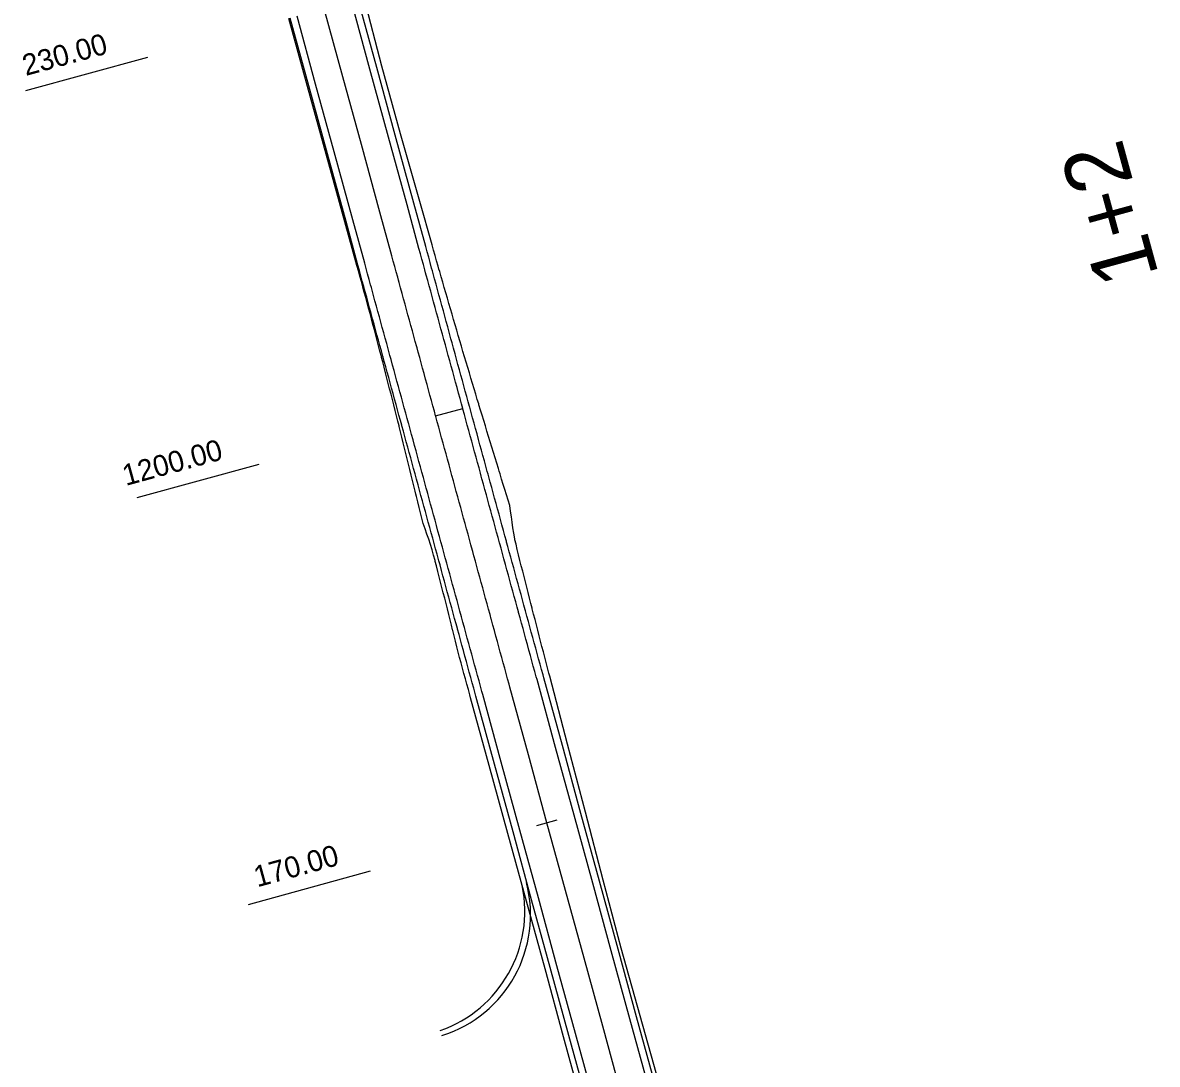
# Model space of a CAD drawing. Extents: x -550605 to -538780, y -1102367 to -1093705.
# Drawn here: x -547384 to -547303.3, y -1101097.8 to -1101023.7 of the extents above; entities that cross this region are included whole.
import ezdxf

# ---------------------------------------------------------------- set-up
doc = ezdxf.new("R2010")
doc.units = 0
for name, color, linetype in [('SIT - hrany vozovky', 7, 'Continuous'), ('SIT - oblouky - hrany', 7, 'Continuous'), ('SIT - oblouky - koruna', 7, 'Continuous'), ('SIT - osa cesty', 7, 'Continuous'), ('SIT - paty násypů', 7, 'Continuous'), ('SIT - staničení po 100m', 7, 'Continuous'), ('SIT - staničení po 30m', 7, 'Continuous')]:
    doc.layers.add(name, color=color, linetype=linetype)

msp = doc.modelspace()

# ---------------------------------------------------------------- linework, layer by layer
at = {"layer": 'SIT - hrany vozovky'}
for points in [[(-547339.531, -1101099.38), (-547340.851, -1101094.558), (-547342.171, -1101089.735), (-547343.491, -1101084.913), (-547344.81, -1101080.09), (-547346.13, -1101075.267), (-547347.45, -1101070.445), (-547347.506, -1101070.243), (-547347.61, -1101069.862), (-547347.714, -1101069.481), (-547347.818, -1101069.1), (-547347.923, -1101068.72), (-547348.027, -1101068.339), (-547348.131, -1101067.958), (-547348.235, -1101067.577), (-547348.339, -1101067.197), (-547348.444, -1101066.816), (-547348.548, -1101066.435), (-547348.652, -1101066.054), (-547348.756, -1101065.674), (-547348.77, -1101065.622), (-547348.86, -1101065.293), (-547348.965, -1101064.912), (-547349.069, -1101064.531), (-547349.173, -1101064.151), (-547349.277, -1101063.77), (-547349.382, -1101063.389), (-547349.486, -1101063.008), (-547349.59, -1101062.627), (-547349.694, -1101062.247), (-547349.798, -1101061.866), (-547349.903, -1101061.485), (-547350.007, -1101061.104), (-547350.09, -1101060.799), (-547350.111, -1101060.724), (-547350.215, -1101060.343), (-547350.319, -1101059.962), (-547350.424, -1101059.581), (-547350.528, -1101059.201), (-547350.632, -1101058.82), (-547350.736, -1101058.439), (-547350.841, -1101058.058), (-547350.945, -1101057.678), (-547351.049, -1101057.297), (-547351.153, -1101056.916), (-547351.257, -1101056.535), (-547351.362, -1101056.155), (-547351.41, -1101055.977), (-547351.466, -1101055.774), (-547351.57, -1101055.393), (-547351.674, -1101055.012), (-547351.778, -1101054.631), (-547351.883, -1101054.251), (-547351.987, -1101053.87), (-547352.091, -1101053.489), (-547352.195, -1101053.108), (-547352.3, -1101052.728), (-547352.404, -1101052.347), (-547352.508, -1101051.966), (-547352.612, -1101051.585), (-547352.716, -1101051.205), (-547352.73, -1101051.154), (-547352.821, -1101050.824), (-547352.925, -1101050.443), (-547353.029, -1101050.062), (-547353.133, -1101049.682), (-547353.237, -1101049.301), (-547353.342, -1101048.92), (-547353.446, -1101048.539), (-547353.55, -1101048.159), (-547353.654, -1101047.778), (-547353.759, -1101047.397), (-547353.863, -1101047.016), (-547353.967, -1101046.635), (-547354.05, -1101046.332), (-547354.071, -1101046.255), (-547354.175, -1101045.874), (-547354.28, -1101045.493), (-547354.384, -1101045.112), (-547354.488, -1101044.732), (-547354.592, -1101044.351), (-547354.696, -1101043.97), (-547354.801, -1101043.589), (-547354.905, -1101043.209), (-547355.009, -1101042.828), (-547355.113, -1101042.447), (-547355.218, -1101042.066), (-547355.322, -1101041.686), (-547355.37, -1101041.509), (-547355.426, -1101041.305), (-547355.53, -1101040.924), (-547355.634, -1101040.543), (-547355.739, -1101040.163), (-547355.843, -1101039.782), (-547356.69, -1101036.686), (-547358.01, -1101031.864), (-547359.33, -1101027.041), (-547360.65, -1101022.218)], [(-547339.048, -1101099.248), (-547340.368, -1101094.426), (-547341.688, -1101089.603), (-547343.008, -1101084.781), (-547344.328, -1101079.958), (-547345.648, -1101075.135), (-547346.968, -1101070.313), (-547347.023, -1101070.111), (-547347.128, -1101069.73), (-547347.232, -1101069.349), (-547347.336, -1101068.968), (-547347.44, -1101068.588), (-547347.544, -1101068.207), (-547347.649, -1101067.826), (-547347.753, -1101067.445), (-547347.857, -1101067.065), (-547347.961, -1101066.684), (-547348.066, -1101066.303), (-547348.17, -1101065.922), (-547348.274, -1101065.542), (-547348.288, -1101065.49), (-547348.378, -1101065.161), (-547348.482, -1101064.78), (-547348.587, -1101064.399), (-547348.691, -1101064.019), (-547348.795, -1101063.638), (-547348.899, -1101063.257), (-547349.003, -1101062.876), (-547349.108, -1101062.495), (-547349.212, -1101062.115), (-547349.316, -1101061.734), (-547349.42, -1101061.353), (-547349.525, -1101060.972), (-547349.608, -1101060.667), (-547349.629, -1101060.592), (-547349.733, -1101060.211), (-547349.837, -1101059.83), (-547349.941, -1101059.449), (-547350.046, -1101059.069), (-547350.15, -1101058.688), (-547350.254, -1101058.307), (-547350.358, -1101057.926), (-547350.462, -1101057.546), (-547350.567, -1101057.165), (-547350.671, -1101056.784), (-547350.775, -1101056.403), (-547350.879, -1101056.023), (-547350.928, -1101055.845), (-547350.984, -1101055.642), (-547351.088, -1101055.261), (-547351.192, -1101054.88), (-547351.296, -1101054.499), (-547351.4, -1101054.119), (-547351.505, -1101053.738), (-547351.609, -1101053.357), (-547351.713, -1101052.976), (-547351.817, -1101052.596), (-547351.921, -1101052.215), (-547352.026, -1101051.834), (-547352.13, -1101051.453), (-547352.234, -1101051.073), (-547352.248, -1101051.022), (-547352.338, -1101050.692), (-547352.443, -1101050.311), (-547352.547, -1101049.93), (-547352.651, -1101049.55), (-547352.755, -1101049.169), (-547352.859, -1101048.788), (-547352.964, -1101048.407), (-547353.068, -1101048.027), (-547353.172, -1101047.646), (-547353.276, -1101047.265), (-547353.38, -1101046.884), (-547353.485, -1101046.503), (-547353.568, -1101046.2), (-547353.589, -1101046.123), (-547353.693, -1101045.742), (-547353.797, -1101045.361), (-547353.902, -1101044.98), (-547354.006, -1101044.6), (-547354.11, -1101044.219), (-547354.214, -1101043.838), (-547354.318, -1101043.457), (-547354.423, -1101043.077), (-547354.527, -1101042.696), (-547354.631, -1101042.315), (-547354.735, -1101041.934), (-547354.839, -1101041.554), (-547354.888, -1101041.377), (-547354.944, -1101041.173), (-547355.048, -1101040.792), (-547355.152, -1101040.411), (-547355.256, -1101040.031), (-547355.361, -1101039.65), (-547356.208, -1101036.554), (-547357.528, -1101031.732), (-547358.848, -1101026.909), (-547360.168, -1101022.086)], [(-547343.389, -1101100.436), (-547344.709, -1101095.614), (-547346.029, -1101090.791), (-547347.349, -1101085.968), (-547348.669, -1101081.146), (-547349.989, -1101076.323), (-547351.308, -1101071.501), (-547351.364, -1101071.299), (-547351.468, -1101070.918), (-547351.572, -1101070.537), (-547351.676, -1101070.156), (-547351.781, -1101069.776), (-547351.885, -1101069.395), (-547351.989, -1101069.014), (-547352.093, -1101068.633), (-547352.197, -1101068.253), (-547352.302, -1101067.872), (-547352.406, -1101067.491), (-547352.51, -1101067.11), (-547352.614, -1101066.73), (-547352.628, -1101066.678), (-547352.719, -1101066.349), (-547352.823, -1101065.968), (-547352.927, -1101065.587), (-547353.031, -1101065.207), (-547353.135, -1101064.826), (-547353.24, -1101064.445), (-547353.344, -1101064.064), (-547353.448, -1101063.683), (-547353.552, -1101063.303), (-547353.656, -1101062.922), (-547353.761, -1101062.541), (-547353.865, -1101062.16), (-547353.948, -1101061.855), (-547353.969, -1101061.78), (-547354.073, -1101061.399), (-547354.178, -1101061.018), (-547354.282, -1101060.637), (-547354.386, -1101060.257), (-547354.49, -1101059.876), (-547354.594, -1101059.495), (-547354.699, -1101059.114), (-547354.803, -1101058.734), (-547354.907, -1101058.353), (-547355.011, -1101057.972), (-547355.115, -1101057.591), (-547355.22, -1101057.21), (-547355.268, -1101057.033), (-547355.324, -1101056.83), (-547355.428, -1101056.449), (-547355.532, -1101056.068), (-547355.637, -1101055.687), (-547355.741, -1101055.307), (-547355.845, -1101054.926), (-547355.949, -1101054.545), (-547356.053, -1101054.164), (-547356.158, -1101053.784), (-547356.262, -1101053.403), (-547356.366, -1101053.022), (-547356.47, -1101052.641), (-547356.574, -1101052.261), (-547356.588, -1101052.21), (-547356.679, -1101051.88), (-547356.783, -1101051.499), (-547356.887, -1101051.118), (-547356.991, -1101050.738), (-547357.096, -1101050.357), (-547357.2, -1101049.976), (-547357.304, -1101049.595), (-547357.408, -1101049.214), (-547357.512, -1101048.834), (-547357.617, -1101048.453), (-547357.721, -1101048.072), (-547357.825, -1101047.691), (-547357.908, -1101047.387), (-547357.929, -1101047.311), (-547358.033, -1101046.93), (-547358.138, -1101046.549), (-547358.242, -1101046.168), (-547358.346, -1101045.788), (-547358.45, -1101045.407), (-547358.555, -1101045.026), (-547358.659, -1101044.645), (-547358.763, -1101044.265), (-547358.867, -1101043.884), (-547358.971, -1101043.503), (-547359.076, -1101043.122), (-547359.18, -1101042.742), (-547359.228, -1101042.565), (-547359.284, -1101042.361), (-547359.388, -1101041.98), (-547359.492, -1101041.599), (-547359.597, -1101041.218), (-547359.701, -1101040.838), (-547360.548, -1101037.742), (-547361.868, -1101032.92), (-547363.188, -1101028.097), (-547364.508, -1101023.274)], [(-547343.871, -1101100.568), (-547345.191, -1101095.746), (-547346.511, -1101090.923), (-547347.831, -1101086.1), (-547349.151, -1101081.278), (-547350.471, -1101076.455), (-547351.791, -1101071.633), (-547351.846, -1101071.431), (-547351.95, -1101071.05), (-547352.054, -1101070.669), (-547352.159, -1101070.288), (-547352.263, -1101069.908), (-547352.367, -1101069.527), (-547352.471, -1101069.146), (-547352.576, -1101068.765), (-547352.68, -1101068.385), (-547352.784, -1101068.004), (-547352.888, -1101067.623), (-547352.992, -1101067.242), (-547353.097, -1101066.862), (-547353.111, -1101066.81), (-547353.201, -1101066.481), (-547353.305, -1101066.1), (-547353.409, -1101065.719), (-547353.513, -1101065.338), (-547353.618, -1101064.958), (-547353.722, -1101064.577), (-547353.826, -1101064.196), (-547353.93, -1101063.815), (-547354.035, -1101063.435), (-547354.139, -1101063.054), (-547354.243, -1101062.673), (-547354.347, -1101062.292), (-547354.431, -1101061.987), (-547354.451, -1101061.912), (-547354.556, -1101061.531), (-547354.66, -1101061.15), (-547354.764, -1101060.769), (-547354.868, -1101060.389), (-547354.972, -1101060.008), (-547355.077, -1101059.627), (-547355.181, -1101059.246), (-547355.285, -1101058.866), (-547355.389, -1101058.485), (-547355.494, -1101058.104), (-547355.598, -1101057.723), (-547355.702, -1101057.342), (-547355.751, -1101057.165), (-547355.806, -1101056.962), (-547355.91, -1101056.581), (-547356.015, -1101056.2), (-547356.119, -1101055.819), (-547356.223, -1101055.439), (-547356.327, -1101055.058), (-547356.431, -1101054.677), (-547356.536, -1101054.296), (-547356.64, -1101053.916), (-547356.744, -1101053.535), (-547356.848, -1101053.154), (-547356.953, -1101052.773), (-547357.057, -1101052.393), (-547357.071, -1101052.342), (-547357.161, -1101052.012), (-547357.265, -1101051.631), (-547357.369, -1101051.25), (-547357.474, -1101050.87), (-547357.578, -1101050.489), (-547357.682, -1101050.108), (-547357.786, -1101049.727), (-547357.89, -1101049.346), (-547357.995, -1101048.966), (-547358.099, -1101048.585), (-547358.203, -1101048.204), (-547358.307, -1101047.823), (-547358.391, -1101047.519), (-547358.412, -1101047.443), (-547358.516, -1101047.062), (-547358.62, -1101046.681), (-547358.724, -1101046.3), (-547358.828, -1101045.92), (-547358.933, -1101045.539), (-547359.037, -1101045.158), (-547359.141, -1101044.777), (-547359.245, -1101044.397), (-547359.349, -1101044.016), (-547359.454, -1101043.635), (-547359.558, -1101043.254), (-547359.662, -1101042.874), (-547359.71, -1101042.697), (-547359.766, -1101042.493), (-547359.871, -1101042.112), (-547359.975, -1101041.731), (-547360.079, -1101041.35), (-547360.183, -1101040.97), (-547361.03, -1101037.874), (-547362.35, -1101033.052), (-547363.67, -1101028.229), (-547364.99, -1101023.406)]]:
    msp.add_lwpolyline(points, dxfattribs=at)
at = {"layer": 'SIT - oblouky - hrany'}
msp.add_arc((-547357.314, -1101086.912), 9, 289.38382, 11.65556, dxfattribs=at)
at = {"layer": 'SIT - oblouky - koruna'}
msp.add_arc((-547356.908, -1101087.171), 9, 287.46315, 14.77752, dxfattribs=at)
at = {"layer": 'SIT - osa cesty'}
msp.add_lwpolyline([(-547341.46, -1101099.908), (-547342.78, -1101095.086), (-547344.1, -1101090.263), (-547345.42, -1101085.441), (-547346.74, -1101080.618), (-547348.059, -1101075.795), (-547349.379, -1101070.973), (-547349.435, -1101070.771), (-547349.539, -1101070.39), (-547349.643, -1101070.009), (-547349.747, -1101069.628), (-547349.852, -1101069.248), (-547349.956, -1101068.867), (-547350.06, -1101068.486), (-547350.164, -1101068.105), (-547350.268, -1101067.725), (-547350.373, -1101067.344), (-547350.477, -1101066.963), (-547350.581, -1101066.582), (-547350.685, -1101066.202), (-547350.699, -1101066.15), (-547350.789, -1101065.821), (-547350.894, -1101065.44), (-547350.998, -1101065.059), (-547351.102, -1101064.679), (-547351.206, -1101064.298), (-547351.311, -1101063.917), (-547351.415, -1101063.536), (-547351.519, -1101063.155), (-547351.623, -1101062.775), (-547351.727, -1101062.394), (-547351.832, -1101062.013), (-547351.936, -1101061.632), (-547352.019, -1101061.327), (-547352.04, -1101061.252), (-547352.144, -1101060.871), (-547352.248, -1101060.49), (-547352.353, -1101060.109), (-547352.457, -1101059.729), (-547352.561, -1101059.348), (-547352.665, -1101058.967), (-547352.77, -1101058.586), (-547352.874, -1101058.206), (-547352.978, -1101057.825), (-547353.082, -1101057.444), (-547353.186, -1101057.063), (-547353.291, -1101056.683), (-547353.339, -1101056.505), (-547353.395, -1101056.302), (-547353.499, -1101055.921), (-547353.603, -1101055.54), (-547353.707, -1101055.159), (-547353.812, -1101054.779), (-547353.916, -1101054.398), (-547354.02, -1101054.017), (-547354.124, -1101053.636), (-547354.229, -1101053.256), (-547354.333, -1101052.875), (-547354.437, -1101052.494), (-547354.541, -1101052.113), (-547354.645, -1101051.733), (-547354.659, -1101051.682), (-547354.75, -1101051.352), (-547354.854, -1101050.971), (-547354.958, -1101050.59), (-547355.062, -1101050.21), (-547355.167, -1101049.829), (-547355.271, -1101049.448), (-547355.375, -1101049.067), (-547355.479, -1101048.687), (-547355.583, -1101048.306), (-547355.688, -1101047.925), (-547355.792, -1101047.544), (-547355.896, -1101047.163), (-547355.979, -1101046.86), (-547356, -1101046.783), (-547356.104, -1101046.402), (-547356.209, -1101046.021), (-547356.313, -1101045.64), (-547356.417, -1101045.26), (-547356.521, -1101044.879), (-547356.626, -1101044.498), (-547356.73, -1101044.117), (-547356.834, -1101043.737), (-547356.938, -1101043.356), (-547357.042, -1101042.975), (-547357.147, -1101042.594), (-547357.251, -1101042.214), (-547357.299, -1101042.037), (-547357.355, -1101041.833), (-547357.459, -1101041.452), (-547357.563, -1101041.071), (-547357.668, -1101040.691), (-547357.772, -1101040.31), (-547358.619, -1101037.214), (-547359.939, -1101032.392), (-547361.259, -1101027.569), (-547362.579, -1101022.746)], dxfattribs=at)
at = {"layer": 'SIT - paty násypů'}
for points in [[(-547338.755, -1101099.168), (-547340.125, -1101094.359), (-547341.465, -1101089.542), (-547342.735, -1101084.706), (-547344.005, -1101079.869), (-547345.275, -1101075.033), (-547346.545, -1101070.197), (-547346.599, -1101069.994), (-547346.699, -1101069.613), (-547346.799, -1101069.231), (-547346.898, -1101068.849), (-547346.998, -1101068.467), (-547347.097, -1101068.085), (-547347.197, -1101067.702), (-547347.296, -1101067.32), (-547347.394, -1101066.938), (-547347.493, -1101066.556), (-547347.592, -1101066.173), (-547347.69, -1101065.791), (-547347.788, -1101065.409), (-547347.801, -1101065.357), (-547347.886, -1101065.026), (-547347.984, -1101064.644), (-547348.081, -1101064.261), (-547348.178, -1101063.878), (-547348.275, -1101063.496), (-547348.372, -1101063.113), (-547348.469, -1101062.73), (-547348.566, -1101062.347), (-547348.66, -1101061.964), (-547348.755, -1101061.58), (-547348.849, -1101061.197), (-547348.943, -1101060.813), (-547349.018, -1101060.506), (-547349.036, -1101060.43), (-547349.1, -1101060.038), (-547349.157, -1101059.644), (-547349.215, -1101059.251), (-547349.272, -1101058.857), (-547349.329, -1101058.463), (-547349.389, -1101058.07), (-547349.501, -1101057.692), (-547349.615, -1101057.314), (-547349.732, -1101056.936), (-547349.848, -1101056.559), (-547349.965, -1101056.181), (-547350.081, -1101055.804), (-547350.135, -1101055.628), (-547350.197, -1101055.426), (-547350.313, -1101055.049), (-547350.428, -1101054.671), (-547350.544, -1101054.294), (-547350.659, -1101053.916), (-547350.775, -1101053.538), (-547350.89, -1101053.161), (-547351.006, -1101052.783), (-547351.121, -1101052.405), (-547351.236, -1101052.027), (-547351.351, -1101051.649), (-547351.465, -1101051.271), (-547351.58, -1101050.893), (-547351.595, -1101050.843), (-547351.694, -1101050.515), (-547351.808, -1101050.137), (-547351.921, -1101049.759), (-547352.035, -1101049.381), (-547352.148, -1101049.003), (-547352.261, -1101048.624), (-547352.374, -1101048.246), (-547352.487, -1101047.868), (-547352.599, -1101047.489), (-547352.712, -1101047.11), (-547352.824, -1101046.732), (-547352.936, -1101046.353), (-547353.025, -1101046.051), (-547353.047, -1101045.974), (-547353.159, -1101045.596), (-547353.27, -1101045.217), (-547353.381, -1101044.838), (-547353.492, -1101044.459), (-547353.602, -1101044.08), (-547353.712, -1101043.701), (-547353.823, -1101043.322), (-547353.933, -1101042.942), (-547354.042, -1101042.563), (-547354.152, -1101042.184), (-547354.261, -1101041.805), (-547354.37, -1101041.425), (-547354.421, -1101041.249), (-547354.479, -1101041.046), (-547354.588, -1101040.666), (-547354.696, -1101040.286), (-547354.804, -1101039.907), (-547354.912, -1101039.527), (-547355.79, -1101036.44), (-547357.154, -1101031.629), (-547358.478, -1101026.808), (-547359.739, -1101021.969)], [(-547344.25, -1101100.672), (-547345.555, -1101095.845), (-547346.866, -1101091.02), (-547348.193, -1101086.2), (-547349.52, -1101081.379), (-547350.847, -1101076.558), (-547352.17, -1101071.736), (-547352.225, -1101071.534), (-547352.329, -1101071.154), (-547352.434, -1101070.773), (-547352.538, -1101070.392), (-547352.643, -1101070.012), (-547352.748, -1101069.631), (-547352.854, -1101069.251), (-547352.956, -1101068.87), (-547353.052, -1101068.486), (-547353.147, -1101068.103), (-547353.243, -1101067.72), (-547353.338, -1101067.337), (-547353.434, -1101066.954), (-547353.447, -1101066.902), (-547353.53, -1101066.571), (-547353.627, -1101066.188), (-547353.723, -1101065.805), (-547353.82, -1101065.422), (-547353.917, -1101065.04), (-547354.014, -1101064.657), (-547354.111, -1101064.274), (-547354.209, -1101063.892), (-547354.307, -1101063.509), (-547354.405, -1101063.127), (-547354.503, -1101062.744), (-547354.601, -1101062.362), (-547354.68, -1101062.056), (-547354.7, -1101061.98), (-547354.798, -1101061.597), (-547354.905, -1101061.217), (-547355.019, -1101060.839), (-547355.14, -1101060.463), (-547355.274, -1101060.09), (-547355.409, -1101059.718), (-547355.543, -1101059.346), (-547355.639, -1101058.962), (-547355.732, -1101058.579), (-547355.825, -1101058.195), (-547355.919, -1101057.811), (-547356.012, -1101057.427), (-547356.056, -1101057.248), (-547356.106, -1101057.044), (-547356.201, -1101056.66), (-547356.295, -1101056.277), (-547356.389, -1101055.894), (-547356.484, -1101055.51), (-547356.579, -1101055.127), (-547356.674, -1101054.744), (-547356.769, -1101054.36), (-547356.865, -1101053.977), (-547356.961, -1101053.594), (-547357.056, -1101053.211), (-547357.152, -1101052.828), (-547357.249, -1101052.445), (-547357.261, -1101052.394), (-547357.345, -1101052.062), (-547357.442, -1101051.679), (-547357.539, -1101051.297), (-547357.636, -1101050.914), (-547357.733, -1101050.531), (-547357.83, -1101050.149), (-547357.928, -1101049.766), (-547358.026, -1101049.383), (-547358.124, -1101049.001), (-547358.222, -1101048.619), (-547358.32, -1101048.236), (-547358.419, -1101047.854), (-547358.498, -1101047.549), (-547358.518, -1101047.472), (-547358.617, -1101047.089), (-547358.716, -1101046.707), (-547358.815, -1101046.325), (-547358.915, -1101045.943), (-547359.014, -1101045.561), (-547359.114, -1101045.179), (-547359.215, -1101044.797), (-547359.318, -1101044.416), (-547359.421, -1101044.035), (-547359.524, -1101043.654), (-547359.628, -1101043.273), (-547359.731, -1101042.892), (-547359.779, -1101042.716), (-547359.835, -1101042.512), (-547359.939, -1101042.131), (-547360.044, -1101041.75), (-547360.148, -1101041.369), (-547360.253, -1101040.989), (-547361.105, -1101037.895), (-547362.433, -1101033.074), (-547363.763, -1101028.254), (-547365.102, -1101023.437)]]:
    msp.add_lwpolyline(points, dxfattribs=at)
at = {"layer": 'SIT - staničení po 100m'}
msp.add_lwpolyline([(-547354.659, -1101051.682), (-547352.73, -1101051.154)], dxfattribs=at)
at = {"layer": 'SIT - staničení po 30m'}
for points in [[(-547383.799, -1101028.554), (-547375.118, -1101026.178)], [(-547375.879, -1101057.49), (-547367.198, -1101055.114)], [(-547347.463, -1101080.816), (-547346.016, -1101080.42)], [(-547367.959, -1101086.426), (-547359.278, -1101084.05)]]:
    msp.add_lwpolyline(points, dxfattribs=at)

# ---------------------------------------------------------------- texts
at = {"layer": 'SIT - staničení po 100m'}
msp.add_text('1+2', height=4.5, rotation=105.30701, dxfattribs=at).set_placement((-547303.225, -1101041.679))
at = {"layer": 'SIT - staničení po 30m'}
for s, p in [('230.00', (-547383.796, -1101027.517)), ('1200.00', (-547376.685, -1101056.674)), ('170.00', (-547367.341, -1101085.22))]:
    msp.add_text(s, height=1.5, rotation=15.30701, dxfattribs=at).set_placement(p)

doc.saveas('drawing.dxf')
